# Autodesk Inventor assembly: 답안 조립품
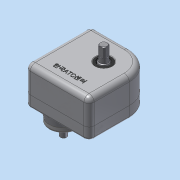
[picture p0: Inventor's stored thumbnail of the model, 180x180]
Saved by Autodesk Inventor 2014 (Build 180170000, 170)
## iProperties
Created: 2015-11
Part Number: 답안 조립품
Document SubType Name: Assembly
Designer: dgall
Author: dgall
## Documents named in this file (13)
- C:\Users\dgall\Desktop\2급\Inventor-2급 장홍은\답안 조립품.iam
- C:\Users\dgall\Desktop\2급\Inventor-2급 장홍은\본체.ipt
- C:\Users\dgall\Desktop\2급\Inventor-2급 장홍은\앞커버.ipt
- C:\Users\dgall\Desktop\2급\Inventor-2급 장홍은\베어링 6002.ipt
- C:\Users\dgall\Desktop\2급\Inventor-2급 장홍은\축 커버.ipt
- C:\Users\dgall\Desktop\2급\Inventor-2급 장홍은\베어링 6001.ipt
- C:\Users\dgall\Desktop\2급\Inventor-2급 장홍은\로드 축.ipt
- C:\Users\dgall\Desktop\2급\Inventor-2급 장홍은\편심 축.ipt
- C:\Users\dgall\Desktop\2급\Inventor-2급 장홍은\로드.ipt
- C:\Users\dgall\Desktop\2급\Inventor-2급 장홍은\오일실 15 x 25.ipt
- C:\Users\dgall\Desktop\2급\Inventor-2급 장홍은\오일실 12 x 22.ipt
- C:\Users\dgall\Desktop\2급\Inventor-2급 장홍은\M4 x 0.7.ipt
- C:\Users\dgall\Desktop\2급\Inventor-2급 장홍은\M3 x 0.5.ipt
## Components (9 placed, 2 different names)
1. M4 x 0.7:1
2. M4 x 0.7:2
3. M4 x 0.7:3
4. M4 x 0.7:4
5. M3 x 0.5:1
6. M3 x 0.5:2
7. M3 x 0.5:3
8. M3 x 0.5:4
9. M4 x 0.7:5
